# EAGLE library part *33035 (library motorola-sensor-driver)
Brushless DC Motor Controller http://onsemi.com; mc33035-d.pdf
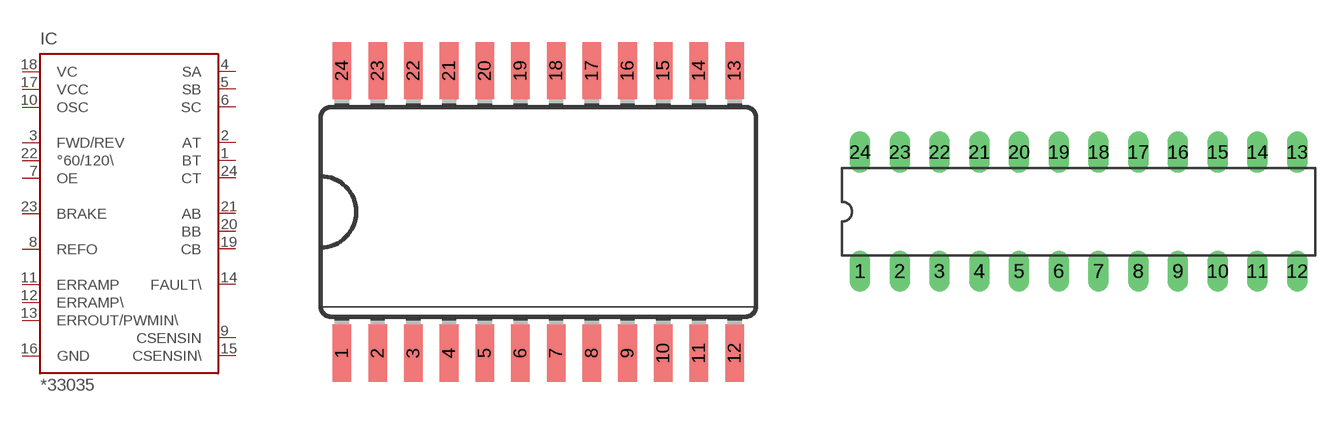
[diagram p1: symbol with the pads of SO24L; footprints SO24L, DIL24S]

Designator prefix IC

## MC33035DW, NCV33035DW  [SO24L]
1  BT  out
2  AT  out
3  FWD/REV  in
4  SA  in
5  SB  in
6  SC  in
7  OE  in
8  REFO  out
9  CSENSIN  in
10  OSC  in
11  ERRAMP  in
12  ERRAMP\  in
13  ERROUT/PWMIN\  pas
14  FAULT\  out
15  CSENSIN\  in
16  GND  pwr
17  VCC  pwr
18  VC  pwr
19  CB  out
20  BB  out
21  AB  out
22  °60/120\  in
23  BRAKE  in
24  CT  out

## 33035P  [DIL24S]
Pads as for SO24L

## Footprint SO24L (pad centres in mm)
Small Outline Package Large SO-24L; Case 751 http://onsemi.com; mc33035-d.pdf
smd 0.66 x 2.032: 1 -6.985,-5.029; 2 -5.715,-5.029; 3 -4.445,-5.029; 4 -3.175,-5.029; 5 -1.905,-5.029; 6 -0.635,-5.029; 7 0.635,-5.029; 8 1.905,-5.029; 9 3.175,-5.029; 10 4.445,-5.029; 11 5.715,-5.029; 12 6.985,-5.029; 13 6.985,5.029; 14 5.715,5.029; 15 4.445,5.029; 16 3.175,5.029; 17 1.905,5.029; 18 0.635,5.029; 19 -0.635,5.029; 20 -1.905,5.029; 21 -3.175,5.029; 22 -4.445,5.029; 23 -5.715,5.029; 24 -6.985,5.029

## Footprint DIL24S (pad centres in mm)
Dual In Line Small
drill 0.813 long: 1 -13.97,-3.81; 2 -11.43,-3.81; 3 -8.89,-3.81; 4 -6.35,-3.81; 5 -3.81,-3.81; 6 -1.27,-3.81; 7 1.27,-3.81; 8 3.81,-3.81; 9 6.35,-3.81; 10 8.89,-3.81; 11 11.43,-3.81; 12 13.97,-3.81; 13 13.97,3.81; 14 11.43,3.81; 15 8.89,3.81; 16 6.35,3.81; 17 3.81,3.81; 18 1.27,3.81; 19 -1.27,3.81; 20 -3.81,3.81; 21 -6.35,3.81; 22 -8.89,3.81; 23 -11.43,3.81; 24 -13.97,3.81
